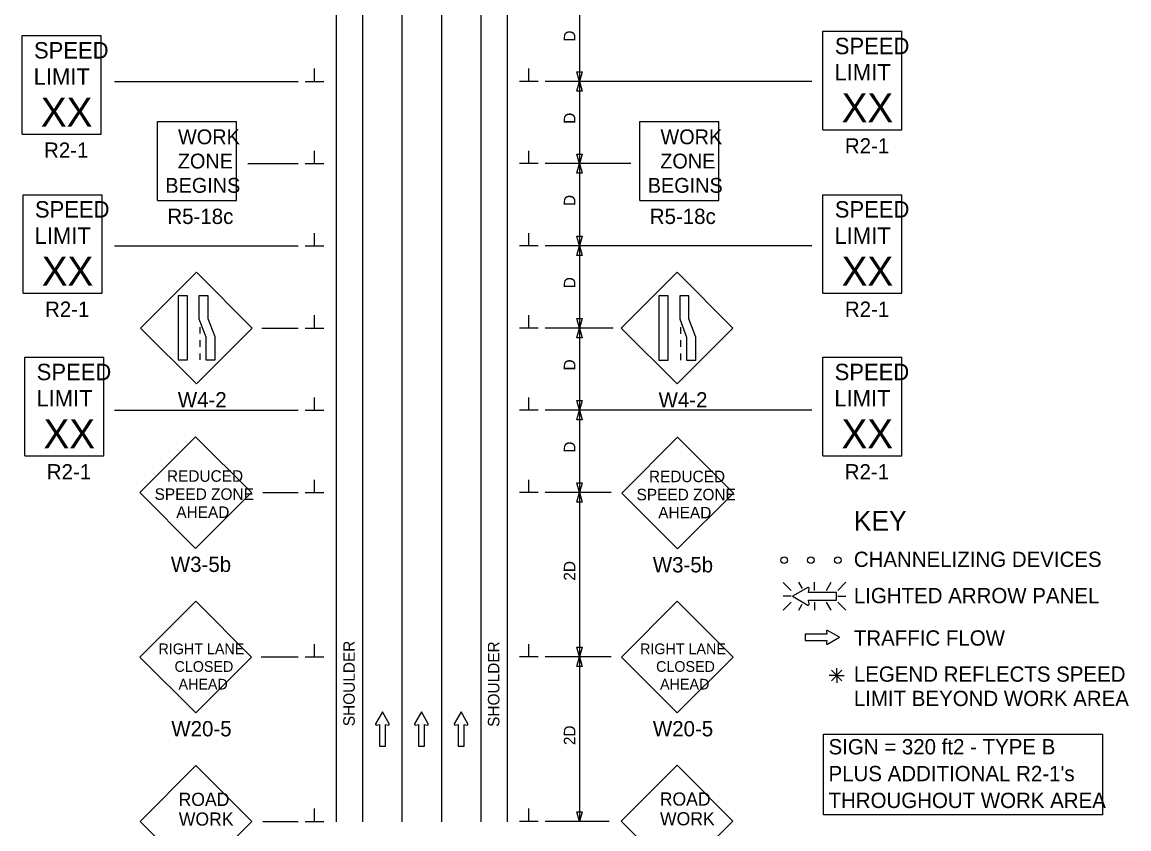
# Model space of a CAD drawing. Extents: x 16734 to 18479, y 5690 to 6925.
# Drawn here: x 16760 to 17433, y 6104 to 6594 of the extents above; entities that cross this region are included whole.
import ezdxf

# ---------------------------------------------------------------- set-up
doc = ezdxf.new("R2010")
doc.units = 0
for name, color, linetype in [('ALI_LEGAL_EX', 7, 'Continuous'), ('MT_SCRATCH_LEVEL_E', 7, 'Continuous'), ('PAVT_EDGE_EX', 7, 'Continuous'), ('TRAFFIC_SIGNS_PR', 7, 'Continuous'), ('TYPICAL_TEXT_DIMEN_EX', 7, 'Continuous'), ('TYPICAL_TEXT_DIMEN_PR', 7, 'Continuous')]:
    doc.layers.add(name, color=color, linetype=linetype)

msp = doc.modelspace()

# ---------------------------------------------------------------- linework, layer by layer
at = {"layer": 'ALI_LEGAL_EX'}
for p, q in [((16991.15, 6924.81), (16991.15, 6107.83)), ((17015.15, 6924.81), (17015.15, 6107.83))]:
    msp.add_line(p, q, dxfattribs=at)
for points in [[(16991.15, 6524.81), (16991.15, 6499.81)], [(17015.15, 6524.81), (17015.15, 6499.81)], [(16991.15, 6474.81), (16991.15, 6449.81)], [(17015.15, 6474.81), (17015.15, 6449.81)], [(16991.15, 6424.81), (16991.15, 6399.81)], [(17015.15, 6424.81), (17015.15, 6399.81)], [(16991.15, 6324.81), (16991.15, 6299.81)], [(17015.15, 6324.81), (17015.15, 6299.81)], [(16991.15, 6224.81), (16991.15, 6199.81)], [(17015.15, 6224.81), (17015.15, 6199.81)], [(16991.15, 6124.81), (16991.15, 6107.83)], [(17015.15, 6124.81), (17015.15, 6107.83)]]:
    msp.add_lwpolyline(points, dxfattribs=at)
at = {"layer": 'MT_SCRATCH_LEVEL_E'}
for p, q in [((17249.21, 6223.79), (17249.52, 6222.01)), ((17257.13, 6220.16), (17249.89, 6224.27)), ((17249.52, 6222.01), (17236.26, 6222.01)), ((17236.26, 6222.01), (17236.26, 6218.27)), ((17236.26, 6218.27), (17249.52, 6218.27)), ((17249.52, 6218.27), (17249.21, 6216.49)), ((17249.89, 6216.01), (17257.13, 6220.16)), ((16979.3, 6174.71), (16975.19, 6167.47)), ((16983.44, 6167.47), (16979.3, 6174.71)), ((17003, 6174.71), (16998.89, 6167.47)), ((17007.15, 6167.47), (17003, 6174.71)), ((17027.11, 6174.71), (17023, 6167.47)), ((17031.26, 6167.47), (17027.11, 6174.71)), ((16975.67, 6166.78), (16977.45, 6167.1)), ((16977.45, 6167.1), (16977.45, 6153.84)), ((16981.19, 6153.84), (16981.19, 6167.1)), ((16981.19, 6167.1), (16982.97, 6166.78)), ((16999.37, 6166.78), (17001.15, 6167.1)), ((17001.15, 6167.1), (17001.15, 6153.84)), ((17004.89, 6153.84), (17004.89, 6167.1)), ((17004.89, 6167.1), (17006.67, 6166.78)), ((17023.48, 6166.78), (17025.26, 6167.1)), ((17025.26, 6167.1), (17025.26, 6153.84)), ((17029, 6153.84), (17029, 6167.1)), ((17029, 6167.1), (17030.78, 6166.78)), ((16977.45, 6153.84), (16981.19, 6153.84)), ((17001.15, 6153.84), (17004.89, 6153.84)), ((17025.26, 6153.84), (17029, 6153.84))]:
    msp.add_line(p, q, dxfattribs=at)
for centre, start, end in [((17249.66, 6223.86), 60.42484, 189.96381), ((17249.66, 6216.42), 170.03619, 299.77312), ((16975.59, 6167.24), 150.42484, 279.96381), ((16983.04, 6167.25), 260.03619, 29.77312), ((16999.3, 6167.24), 150.42484, 279.96381), ((17006.74, 6167.25), 260.03619, 29.77312), ((17023.41, 6167.24), 150.42484, 279.96381), ((17030.85, 6167.25), 260.03619, 29.77312)]:
    msp.add_arc(centre, 0.463, start, end, dxfattribs=at)
at = {"layer": 'PAVT_EDGE_EX'}
for p, q in [((16951.15, 6923.54), (16951.15, 6107.83)), ((16967.15, 6923.54), (16967.15, 6107.83)), ((17039.15, 6923.54), (17039.15, 6107.83)), ((17055.15, 6923.54), (17055.15, 6107.83))]:
    msp.add_line(p, q, dxfattribs=at)
at = {"layer": 'TRAFFIC_SIGNS_PR'}
for p, q in [((17247.11, 6588.68), (17295.11, 6588.68)), ((17247.11, 6528.68), (17247.11, 6588.68)), ((17295.11, 6528.68), (17295.11, 6588.68)), ((16760.29, 6586.05), (16808.29, 6586.05)), ((16760.29, 6526.05), (16760.29, 6586.05)), ((16808.29, 6526.05), (16808.29, 6586.05)), ((16842.58, 6485.79), (16842.58, 6533.79)), ((16842.58, 6533.79), (16890.58, 6533.79)), ((16890.58, 6485.79), (16890.58, 6533.79)), ((17135.85, 6485.79), (17135.85, 6533.79)), ((17135.85, 6533.79), (17183.85, 6533.79)), ((17183.85, 6485.79), (17183.85, 6533.79)), ((17247.11, 6528.68), (17295.11, 6528.68)), ((16760.29, 6526.05), (16808.29, 6526.05)), ((16760.86, 6489.32), (16808.86, 6489.32)), ((16760.86, 6429.32), (16760.86, 6489.32)), ((16808.86, 6429.32), (16808.86, 6489.32)), ((16842.58, 6485.79), (16890.58, 6485.79)), ((17135.85, 6485.79), (17183.85, 6485.79)), ((17247.11, 6489.32), (17295.11, 6489.32)), ((17247.11, 6429.32), (17247.11, 6489.32)), ((17295.11, 6429.32), (17295.11, 6489.32)), ((16866.22, 6442.13), (16832.28, 6408.19)), ((16900.16, 6408.19), (16866.22, 6442.13)), ((17158.48, 6442.09), (17124.54, 6408.15)), ((17192.42, 6408.15), (17158.48, 6442.09)), ((16760.86, 6429.32), (16808.86, 6429.32)), ((17247.11, 6429.32), (17295.11, 6429.32)), ((16832.28, 6408.19), (16866.22, 6374.25)), ((16866.22, 6374.25), (16900.16, 6408.19)), ((16868.27, 6408.81), (16868.27, 6404.81)), ((17124.54, 6408.15), (17158.48, 6374.2)), ((17158.48, 6374.2), (17192.42, 6408.15)), ((17160.53, 6408.76), (17160.53, 6404.76)), ((16868.27, 6400.81), (16868.27, 6396.81)), ((17160.53, 6400.76), (17160.53, 6396.76)), ((16868.27, 6392.81), (16868.27, 6388.81)), ((17160.53, 6392.76), (17160.53, 6388.76)), ((16761.93, 6390.42), (16809.93, 6390.42)), ((16761.93, 6330.42), (16761.93, 6390.42)), ((16809.93, 6330.42), (16809.93, 6390.42)), ((17247.01, 6390.42), (17295.01, 6390.42)), ((17247.01, 6330.42), (17247.01, 6390.42)), ((17295.01, 6330.42), (17295.01, 6390.42)), ((16865.75, 6342.03), (16831.81, 6308.09)), ((16899.69, 6308.09), (16865.75, 6342.03)), ((17158.74, 6341.77), (17124.8, 6307.82)), ((17192.68, 6307.82), (17158.74, 6341.77)), ((16761.93, 6330.42), (16809.93, 6330.42)), ((17247.01, 6330.42), (17295.01, 6330.42)), ((16831.81, 6308.09), (16865.75, 6274.15)), ((16865.75, 6274.15), (16899.69, 6308.09)), ((17124.8, 6307.82), (17158.74, 6273.88)), ((17158.74, 6273.88), (17192.68, 6307.82)), ((17222.94, 6253.54), (17227.87, 6248.61)), ((17234.7, 6249.72), (17232.5, 6253.55)), ((17242.02, 6248.61), (17242.02, 6253.55)), ((17249.26, 6248.61), (17252.11, 6253.55)), ((17256.17, 6248.61), (17261.11, 6253.55)), ((17227.87, 6245.06), (17222.94, 6245.06)), ((17256.17, 6245.06), (17261.11, 6245.06)), ((16865.78, 6242.06), (16831.84, 6208.12)), ((16899.72, 6208.12), (16865.78, 6242.06)), ((17158.53, 6242.06), (17124.58, 6208.12)), ((17192.47, 6208.12), (17158.53, 6242.06)), ((17222.94, 6236.57), (17227.87, 6241.5)), ((17232.45, 6236.57), (17234.56, 6240.23)), ((17242.02, 6241.5), (17242.02, 6236.57)), ((17252.15, 6236.57), (17249.3, 6241.5)), ((17256.17, 6241.5), (17261.11, 6236.56)), ((16831.84, 6208.12), (16865.78, 6174.18)), ((16865.78, 6174.18), (16899.72, 6208.12)), ((17124.58, 6208.12), (17158.53, 6174.18)), ((17158.53, 6174.18), (17192.47, 6208.12)), ((16865.95, 6142.09), (16832.01, 6108.15)), ((16899.9, 6108.15), (16865.95, 6142.09)), ((17158.48, 6142.28), (17124.54, 6108.34)), ((17192.42, 6108.34), (17158.48, 6142.28)), ((16832.01, 6108.15), (16865.95, 6074.21)), ((16865.95, 6074.21), (16899.9, 6108.15)), ((17124.54, 6108.34), (17158.48, 6074.4)), ((17158.48, 6074.4), (17192.42, 6108.34))]:
    msp.add_line(p, q, dxfattribs=at)
for points in [[(16855.1, 6427.86), (16855.1, 6388.81), (16860.72, 6388.81), (16860.72, 6427.86)], [(16867.77, 6427.86), (16867.77, 6413.89), (16871.95, 6402.78), (16871.95, 6388.81), (16877.57, 6388.81), (16877.57, 6402.78), (16873.39, 6413.89), (16873.39, 6427.86)], [(17147.36, 6427.82), (17147.36, 6388.76), (17152.98, 6388.76), (17152.98, 6427.82)], [(17160.03, 6427.82), (17160.03, 6413.84), (17164.21, 6402.74), (17164.21, 6388.76), (17169.83, 6388.76), (17169.83, 6402.74), (17165.65, 6413.84), (17165.65, 6427.82)]]:
    msp.add_lwpolyline(points, close=True, dxfattribs=at)
for points in [[(17237.95, 6250.33), (17228.66, 6245.06), (17237.95, 6239.73)], [(17238.83, 6240.36), (17238.42, 6242.63), (17255.44, 6242.63), (17255.44, 6247.43), (17238.42, 6247.43), (17238.83, 6249.71)]]:
    msp.add_lwpolyline(points, dxfattribs=at)
for centre in [(17223.5, 6267.09), (17239.8, 6267.09), (17256.1, 6267.09)]:
    msp.add_circle(centre, 2, dxfattribs=at)
for centre, radius, start, end in [((17238.24, 6249.81), 0.598, 350.73078, 118.89165), ((17238.24, 6240.26), 0.597, 241.48329, 9.95933)]:
    msp.add_arc(centre, radius, start, end, dxfattribs=at)
at = {"layer": 'TYPICAL_TEXT_DIMEN_EX'}
msp.add_lwpolyline([(17247.5, 6161.3), (17416.95, 6161.3), (17416.95, 6112.11), (17247.5, 6112.11)], close=True, dxfattribs=at)
at = {"layer": 'TYPICAL_TEXT_DIMEN_PR'}
for p, q in [((17099.15, 6608.18), (17099.15, 6558.18)), ((16938.03, 6558.18), (16938.03, 6565.97)), ((17068.28, 6558.18), (17068.28, 6565.97)), ((17099.15, 6558.18), (17097.58, 6564.04)), ((17097.58, 6564.04), (17099.15, 6564.04)), ((17099.15, 6564.04), (17100.72, 6564.04)), ((17100.72, 6564.04), (17099.15, 6558.18)), ((16816.41, 6558.18), (16928.15, 6558.18)), ((16932.4, 6558.18), (16943.65, 6558.18)), ((17073.9, 6558.18), (17062.65, 6558.18)), ((17240.31, 6558.18), (17078.15, 6558.18)), ((17097.58, 6552.32), (17099.15, 6558.18)), ((17099.15, 6558.18), (17099.15, 6508.18)), ((17099.15, 6558.18), (17100.72, 6552.32)), ((17099.15, 6552.32), (17097.58, 6552.32)), ((17100.72, 6552.32), (17099.15, 6552.32)), ((16938.03, 6508.18), (16938.03, 6515.97)), ((17068.28, 6508.18), (17068.28, 6515.97)), ((17099.15, 6508.18), (17097.58, 6514.04)), ((17097.58, 6514.04), (17099.15, 6514.04)), ((17099.15, 6514.04), (17100.72, 6514.04)), ((17100.72, 6514.04), (17099.15, 6508.18)), ((16897.4, 6508.18), (16928.15, 6508.18)), ((16932.4, 6508.18), (16943.65, 6508.18)), ((17073.9, 6508.18), (17062.65, 6508.18)), ((17130.36, 6508.18), (17078.15, 6508.18)), ((17097.58, 6502.32), (17099.15, 6508.18)), ((17099.15, 6508.18), (17099.15, 6458.18)), ((17099.15, 6508.18), (17100.72, 6502.32)), ((17099.15, 6502.32), (17097.58, 6502.32)), ((17100.72, 6502.32), (17099.15, 6502.32)), ((16938.03, 6458.18), (16938.03, 6465.97)), ((17068.28, 6458.18), (17068.28, 6465.97)), ((17099.15, 6458.18), (17097.58, 6464.04)), ((17097.58, 6464.04), (17099.15, 6464.04)), ((17099.15, 6464.04), (17100.72, 6464.04)), ((17100.72, 6464.04), (17099.15, 6458.18)), ((16816.41, 6458.18), (16928.15, 6458.18)), ((16932.4, 6458.18), (16943.65, 6458.18)), ((17073.9, 6458.18), (17062.65, 6458.18)), ((17240.31, 6458.18), (17078.15, 6458.18)), ((17097.58, 6452.32), (17099.15, 6458.18)), ((17099.15, 6452.32), (17097.58, 6452.32)), ((17099.15, 6458.18), (17099.15, 6408.18)), ((17099.15, 6458.18), (17100.72, 6452.32)), ((17100.72, 6452.32), (17099.15, 6452.32)), ((16938.03, 6408.18), (16938.03, 6415.97)), ((17068.28, 6408.18), (17068.28, 6415.97)), ((17099.15, 6408.18), (17097.58, 6414.04)), ((17097.58, 6414.04), (17099.15, 6414.04)), ((17099.15, 6414.04), (17100.72, 6414.04)), ((17100.72, 6414.04), (17099.15, 6408.18)), ((16906.06, 6408.18), (16928.15, 6408.18)), ((16932.4, 6408.18), (16943.65, 6408.18)), ((17073.9, 6408.18), (17062.65, 6408.18)), ((17119.65, 6408.18), (17078.15, 6408.18)), ((17097.58, 6402.32), (17099.15, 6408.18)), ((17099.15, 6408.18), (17099.15, 6358.18)), ((17099.15, 6408.18), (17100.72, 6402.32)), ((17099.15, 6402.32), (17097.58, 6402.32)), ((17100.72, 6402.32), (17099.15, 6402.32)), ((16938.03, 6358.18), (16938.03, 6365.97)), ((17068.28, 6358.18), (17068.28, 6365.97)), ((16816.41, 6358.18), (16928.15, 6358.18)), ((16932.4, 6358.18), (16943.65, 6358.18)), ((17073.9, 6358.18), (17062.65, 6358.18)), ((17240.31, 6358.18), (17078.15, 6358.18)), ((17099.15, 6358.18), (17097.58, 6364.04)), ((17097.58, 6364.04), (17099.15, 6364.04)), ((17097.58, 6352.32), (17099.15, 6358.18)), ((17099.15, 6364.04), (17100.72, 6364.04)), ((17100.72, 6364.04), (17099.15, 6358.18)), ((17099.15, 6358.18), (17099.15, 6308.18)), ((17099.15, 6358.18), (17100.72, 6352.32)), ((17099.15, 6352.32), (17097.58, 6352.32)), ((17100.72, 6352.32), (17099.15, 6352.32)), ((16938.03, 6308.18), (16938.03, 6315.97)), ((17068.28, 6308.18), (17068.28, 6315.97)), ((17099.15, 6308.18), (17097.58, 6314.04)), ((17097.58, 6314.04), (17099.15, 6314.04)), ((17099.15, 6314.04), (17100.72, 6314.04)), ((17100.72, 6314.04), (17099.15, 6308.18)), ((16906.59, 6308.18), (16928.15, 6308.18)), ((16932.4, 6308.18), (16943.65, 6308.18)), ((17073.9, 6308.18), (17062.65, 6308.18)), ((17118.3, 6308.18), (17078.15, 6308.18)), ((17097.58, 6302.32), (17099.15, 6308.18)), ((17099.15, 6308.18), (17099.15, 6208.18)), ((17099.15, 6308.18), (17100.72, 6302.32)), ((17099.15, 6302.32), (17097.58, 6302.32)), ((17100.72, 6302.32), (17099.15, 6302.32)), ((16938.03, 6208.18), (16938.03, 6215.97)), ((17068.28, 6208.18), (17068.28, 6215.97)), ((17099.15, 6208.18), (17097.58, 6214.04)), ((17097.58, 6214.04), (17099.15, 6214.04)), ((17099.15, 6214.04), (17100.72, 6214.04)), ((17100.72, 6214.04), (17099.15, 6208.18)), ((16905.52, 6208.18), (16928.15, 6208.18)), ((16932.4, 6208.18), (16943.65, 6208.18)), ((17073.9, 6208.18), (17062.65, 6208.18)), ((17118.3, 6208.18), (17078.15, 6208.18)), ((17097.58, 6202.32), (17099.15, 6208.18)), ((17099.15, 6208.18), (17099.15, 6108.18)), ((17099.15, 6208.18), (17100.72, 6202.32)), ((17099.15, 6202.32), (17097.58, 6202.32)), ((17100.72, 6202.32), (17099.15, 6202.32)), ((17255.46, 6196.91), (17250.93, 6196.91)), ((17252.28, 6200.1), (17258.65, 6193.73)), ((17258.65, 6200.1), (17252.28, 6193.73)), ((17255.46, 6196.91), (17255.46, 6201.37)), ((17255.46, 6196.91), (17258.65, 6196.91)), ((17255.46, 6196.91), (17259.94, 6196.91)), ((17255.46, 6196.91), (17255.46, 6192.41)), ((16938.03, 6108.18), (16938.03, 6115.97)), ((17068.28, 6108.18), (17068.28, 6115.97)), ((17099.15, 6108.18), (17097.58, 6114.04)), ((17097.58, 6114.04), (17099.15, 6114.04)), ((17099.15, 6114.04), (17100.72, 6114.04)), ((17100.72, 6114.04), (17099.15, 6108.18)), ((16906.59, 6108.18), (16928.15, 6108.18)), ((16932.4, 6108.18), (16943.65, 6108.18)), ((17073.9, 6108.18), (17062.65, 6108.18)), ((17117.23, 6108.18), (17078.15, 6108.18))]:
    msp.add_line(p, q, dxfattribs=at)

# ---------------------------------------------------------------- texts
at = {"layer": 'TRAFFIC_SIGNS_PR'}
for s, height, p in [('SPEED', 10, (16767.5, 6572.13)), ('SPEED', 10, (17254.32, 6574.76)), ('LIMIT', 10, (17254.12, 6558.76)), ('LIMIT', 10, (16767.29, 6556.13)), ('XX', 17.538, (16771.68, 6530.75)), ('XX', 17.538, (17258.5, 6533.38)), ('WORK', 9.021, (16855.08, 6520)), ('WORK', 9.021, (17148.35, 6520)), ('R2-1', 9.3, (16773.63, 6511.76)), ('R2-1', 9.3, (17260.46, 6514.38)), ('ZONE', 9.021, (16854.93, 6505.24)), ('ZONE', 9.021, (17148.2, 6505.24)), ('BEGINS', 9.021, (16847.34, 6490.47)), ('BEGINS', 9.021, (17140.61, 6490.47)), ('SPEED', 10, (16768.07, 6475.4)), ('R5-18c', 9.3, (16848.59, 6471.49)), ('R5-18c', 9.3, (17141.86, 6471.49)), ('SPEED', 10, (17254.32, 6475.4)), ('LIMIT', 10, (16767.87, 6459.4)), ('LIMIT', 10, (17254.12, 6459.4)), ('XX', 17.538, (16772.25, 6434.02)), ('XX', 17.538, (17258.5, 6434.02)), ('R2-1', 9.3, (16774.21, 6415.02)), ('R2-1', 9.3, (17260.46, 6415.02)), ('SPEED', 10, (16769.14, 6376.5)), ('SPEED', 10, (17254.22, 6376.5)), ('LIMIT', 10, (16768.94, 6360.5)), ('W4-2', 9.3, (16854.92, 6359.95)), ('W4-2', 9.3, (17147.18, 6359.9)), ('LIMIT', 10, (17254.02, 6360.5)), ('XX', 17.538, (16773.32, 6335.12)), ('XX', 17.538, (17258.41, 6335.12)), ('R2-1', 9.3, (16775.28, 6316.13)), ('R2-1', 9.3, (17260.36, 6316.13)), ('REDUCED', 7, (16848.32, 6314.72)), ('REDUCED', 7, (17141.31, 6314.46)), ('SPEED ZONE', 7, (16840.81, 6303.72)), ('SPEED ZONE', 7, (17133.8, 6303.46)), ('AHEAD', 7, (16854.01, 6292.72)), ('AHEAD', 7, (17147, 6292.46)), ('W3-5b', 9.3, (16850.69, 6259.85)), ('W3-5b', 9.3, (17143.68, 6259.58)), ('RIGHT LANE', 6.5, (16843.18, 6209.86)), ('RIGHT LANE', 6.5, (17135.93, 6209.86)), ('CLOSED', 6.5, (16852.92, 6199.11)), ('CLOSED', 6.5, (17145.67, 6199.11)), ('AHEAD', 6.5, (16855.35, 6188.36)), ('AHEAD', 6.5, (17148.1, 6188.36)), ('W20-5', 9.3, (16850.99, 6159.88)), ('W20-5', 9.3, (17143.74, 6159.88)), ('ROAD', 8, (16855.38, 6117.57)), ('ROAD', 8, (17147.91, 6117.76)), ('WORK', 8, (16855.52, 6105.57)), ('WORK', 8, (17148.04, 6105.76))]:
    msp.add_text(s, height=height, dxfattribs=at).set_placement(p)
at = {"layer": 'TYPICAL_TEXT_DIMEN_EX'}
for s, height, p in [('KEY', 12, (17265.88, 6284.95)), ('CHANNELIZING DEVICES', 9.3, (17265.88, 6262.9)), ('LIGHTED ARROW PANEL', 9.3, (17265.88, 6240.85)), ('TRAFFIC FLOW', 9.3, (17265.88, 6215.05)), ('LEGEND REFLECTS SPEED', 9.3, (17265.88, 6193.1)), ('LIMIT BEYOND WORK AREA', 9.3, (17265.88, 6178.3)), ('SIGN = 320 ft2 - TYPE B', 9.3, (17250.51, 6148.9)), ("PLUS ADDITIONAL R2-1's", 9.3, (17250.51, 6132.6)), ('THROUGHOUT WORK AREA', 9.3, (17250.51, 6116.3))]:
    msp.add_text(s, height=height, dxfattribs=at).set_placement(p)
at = {"layer": 'TYPICAL_TEXT_DIMEN_PR'}
for s, p in [('D', (17096.59, 6582.4)), ('D', (17096.59, 6532.4)), ('D', (17096.59, 6482.4)), ('D', (17096.59, 6432.4)), ('D', (17096.59, 6382.4)), ('D', (17096.59, 6332.4)), ('2D', (17096.59, 6254.55)), ('SHOULDER', (16962.51, 6166.05)), ('SHOULDER', (17050.43, 6165.64)), ('2D', (17096.59, 6154.55))]:
    msp.add_text(s, height=7, rotation=90, dxfattribs=at).set_placement(p)

doc.saveas('drawing.dxf')
